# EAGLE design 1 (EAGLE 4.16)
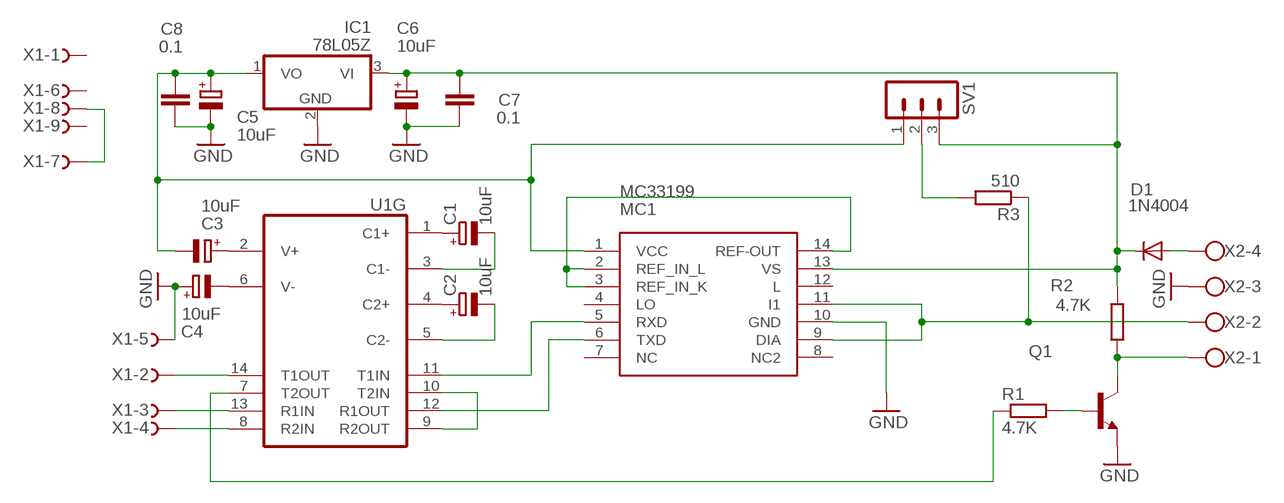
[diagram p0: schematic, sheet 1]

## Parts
C1  10uF  CPOL-EUE2-4  [E2-4]
C2  10uF  CPOL-EUE2-4  [E2-4]
C3  10uF  CPOL-EUE2-4  [E2-4]
C4  10uF  CPOL-EUE2-4  [E2-4]
C5  10uF  CPOL-EUE2-4  [E2-4]
C6  10uF  CPOL-EUE2-4  [E2-4]
C7  0.1  C-EU050-024X044  [C050-024X044]
C8  0.1  C-EU050-024X044  [C050-024X044]
D1  1N4004  [DO41-10]
IC1  78L05Z  [TO92]
MC1  MC33199  [SO14]
Q1  BF459  [TO126]
R1  4.7K  R-EU_0207/10  [0207/10]
R2  4.7K  R-EU_0207/10  [0207/10]
R3  510  R-EU_0207/10  [0207/10]
SV1  MA03-1  [MA03-1]
U1  MAX3232S  [SO16]
X1  F09HPS  [F09HP]
X2  W237-4  [W237-4]

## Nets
12V: C6.+ C7.2 D1.C IC1.3(VI) MC1.13(VS) R2.2 SV1.3
16: R1.1 U1.7(G:T2OUT)
18: MC1.5(RXD) U1.11(G:T1IN)
19: MC1.6(TXD) U1.12(G:R1OUT)
GND: C4.+ C5.- C6.- C7.1 C8.1 IC1.2(GND) MC1.10(GND) Q1.1(E) X1.5 X2.3
N$1: C1.+ U1.1(G:C1+)
N$2: C1.- U1.3(G:C1-)
N$3: C2.+ U1.4(G:C2+)
N$4: C2.- U1.5(G:C2-)
N$5: C3.+ U1.2(G:V+)
N$6: C4.- U1.6(G:V-)
N$7: U1.14(G:T1OUT) X1.2
N$8: R3.2 SV1.2
N$9: U1.13(G:R1IN) X1.3
N$10: U1.8(G:R2IN) X1.4
N$11: U1.9(G:R2OUT) U1.10(G:T2IN)
N$12: D1.A X2.4
N$13: MC1.2(REF_IN_L) MC1.3(REF_IN_K) MC1.14(REF-OUT)
N$14: Q1.3(B) R1.2
N$15: Q1.2(C) R2.1 X2.1
N$16: X1.7 X1.8
N$20: MC1.9(DIA) MC1.11(I1) R3.1 X2.2
VCC: C3.- C5.+ C8.2 IC1.1(VO) MC1.1(VCC) SV1.1
Unconnected: MC1.4(LO) MC1.7(NC) MC1.8(NC2) MC1.12(L) X1.1 X1.6 X1.9

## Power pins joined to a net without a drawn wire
GND: U1.15(P:GND)
VCC: U1.16(P:VCC)

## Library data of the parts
C1-C6 = rcl:CPOL-EU: POLARIZED CAPACITOR, European symbol
C7 C8 = rcl:C-EU: CAPACITOR, European symbol
D1 = diode:1N4004: DIODE
IC1 = linear:78*: Positive VOLTAGE REGULATOR Source: http://cache.national.com/ds/LM/LM78L05.pdf http://www.fairchildsemi.com/ds/LM/LM7805.pdf
MC1 = LevoROMS:MC33199
Q1 = transistor-npn:BF459*: NPN Transistor
R1-R3 = rcl:R-EU_: RESISTOR, European symbol
SV1 = con-lstb:MA03-1: PIN HEADER
U1 = m-pad-2.1:MAX3232: max3232CD or max3232ID digikey parts: 296-13094-1-ND and 296-13098-1-ND respectively ~$2.60 (both 16pin soic narrow, but with different temperature grades) Texas Instruments 3V to 5.5V 250kbit multichannel RS-232 line driver/receiver with +-15kV ESD protection available as TI samples and digikey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
X1 = con-subd:F09?S: SUB-D
X2 = con-wago-500:W237-4: WAGO SCREW CLAMP

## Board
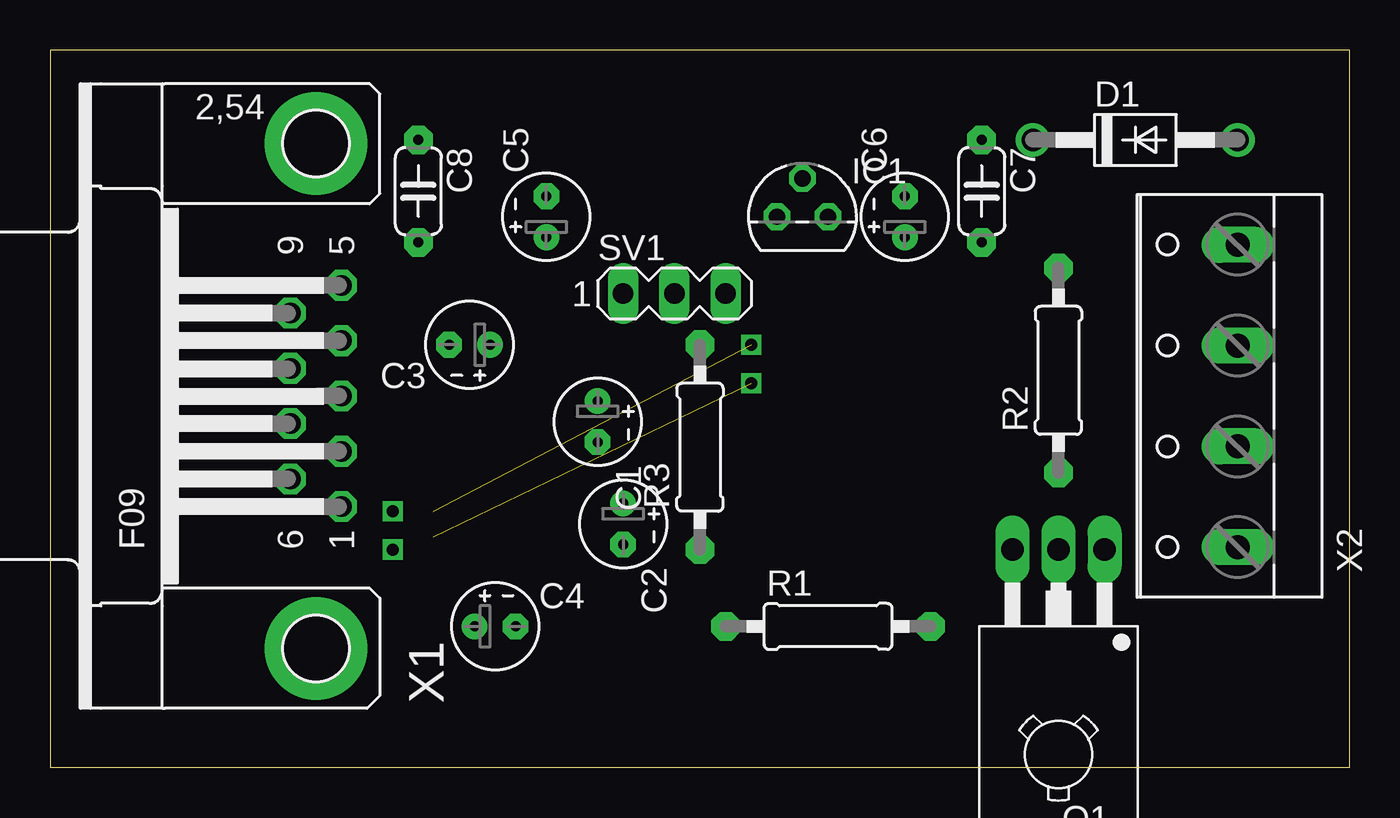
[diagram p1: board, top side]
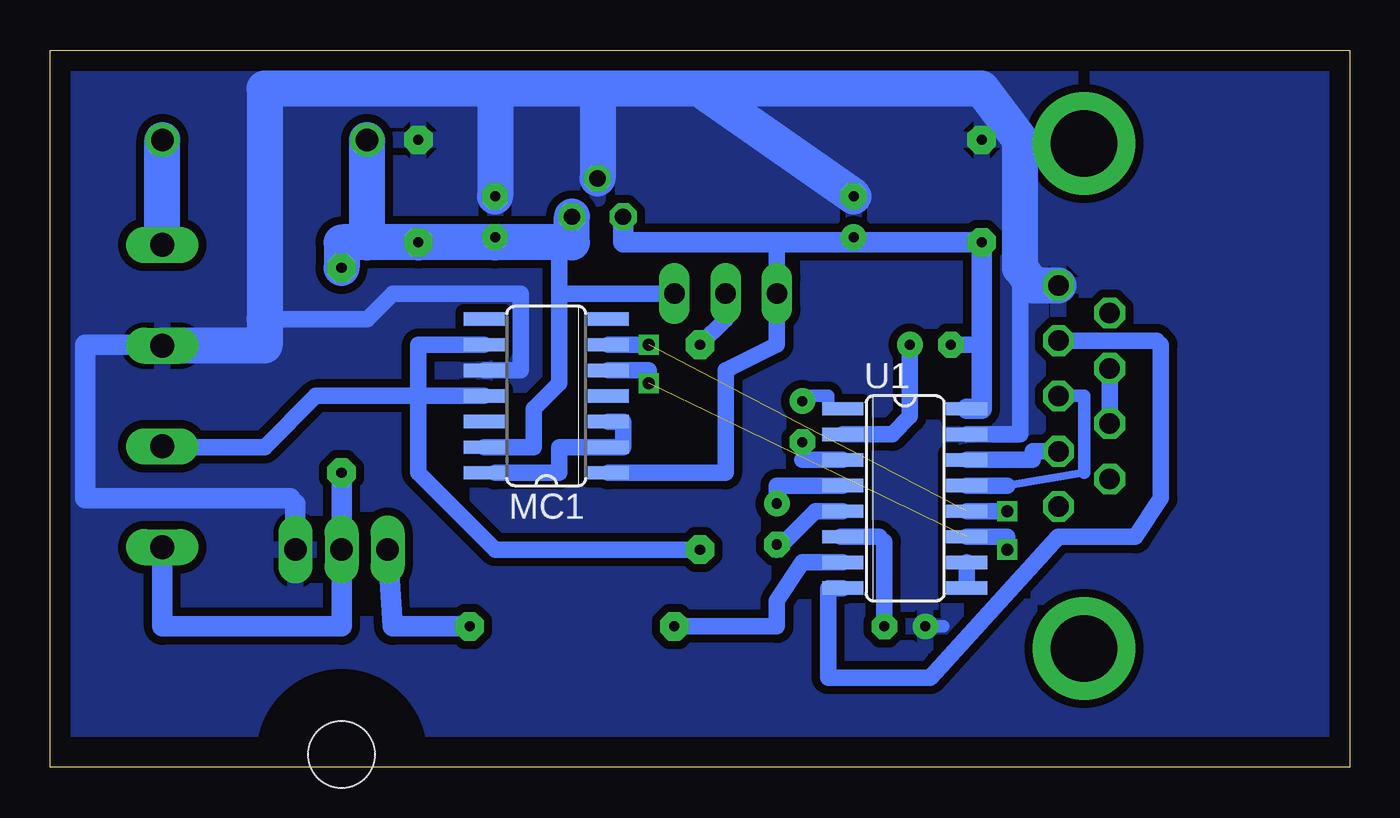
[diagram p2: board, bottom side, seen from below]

Size 64.44 x 35.55 mm. Coordinates in mm from the lower left corner, seen from the top.
Outline: 0,0 64.44,0 64.44,35.55 0,35.55 0,0
Copper layers (1*16): Top 0.035mm / dielectric 1.5mm / Bottom 0.035mm
Design rules "default": minimum track width 10mil, minimum drill 24mil, track to track 8mil, track to pad 8mil, pad to pad 8mil, via to via 8mil, smd to smd 8mil, copper to edge 40mil, drill to drill 8mil, minimum pad ring 10mil, minimum via ring 8mil, stop-mask expansion 4mil, vias tented up to drill 0mil, thermal gap 10mil

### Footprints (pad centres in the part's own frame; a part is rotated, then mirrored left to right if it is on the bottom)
E2-4 = drill 0.5 pad 1.27 round: + -1.016,0 | drill 0.5 pad 1.27 octagon: - 1.016,0
C050-024X044 = drill 0.5 pad 1.422 octagon: 1 -2.54,0; 2 2.54,0
DO41-10 = drill 1.118 round: A 5.08,0; C -5.08,0
TO92 = drill 0.813 octagon: 1 -1.27,0; 2 0,1.905; 3 1.27,0
SO14 = smd 0.66 x 2.032: 1 -3.81,-3.073; 2 -2.54,-3.073; 3 -1.27,-3.073; 4 0,-3.073; 5 1.27,-3.073; 6 2.54,-3.073; 7 3.81,-3.073; 8 3.81,3.073; 9 2.54,3.073; 10 1.27,3.073; 11 0,3.073; 12 -1.27,3.073; 13 -2.54,3.073; 14 -3.81,3.073
TO126 = drill 1.118 long: 1 -2.286,-5.08; 2 0,-5.08; 3 2.286,-5.08 | hole 3.302: 0,5.08
0207/10 = drill 0.5 pad 1.422 octagon: 1 -5.08,0; 2 5.08,0
MA03-1 = drill 1.016 long: 1 -2.54,0; 2 0,0; 3 2.54,0
SO16 = smd 0.66 x 2.032: 1 -4.445,-3.073; 2 -3.175,-3.073; 3 -1.905,-3.073; 4 -0.635,-3.073; 5 0.635,-3.073; 6 1.905,-3.073; 7 3.175,-3.073; 8 4.445,-3.073; 9 4.445,3.073; 10 3.175,3.073; 11 1.905,3.073; 12 0.635,3.073; 13 -0.635,3.073; 14 -1.905,3.073; 15 -3.175,3.073; 16 -4.445,3.073
F09HP = drill 1.016 octagon: 1 -5.486,-1.27; 2 -2.743,-1.27; 3 0,-1.27; 4 2.743,-1.27; 5 5.486,-1.27; 6 -4.115,1.27; 7 -1.372,1.27; 8 1.372,1.27; 9 4.115,1.27 | drill 3.302 pad 5.08 round: G1 -12.522,0; G2 12.522,0
W237-4 = drill 1.194 long: 1 -7.5,-1.27; 2 -2.5,-1.27; 3 2.5,-1.27; 4 7.5,-1.27

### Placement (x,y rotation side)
C1  27.14,17.14 270 top
C2  28.41,12.06 270 top
C3  20.79,20.95 180 top
C4  22.06,6.98 0 top
C5  24.6,27.3 90 top
C6  42.38,27.3 90 top
C7  46.19,28.57 270 top
C8  18.25,28.57 270 top
D1  53.81,31.11 0 top
IC1  37.3,27.3 0 top
MC1  39.84,18.41 90 bottom
Q1  50,5.71 180 top
R1  38.57,6.98 0 top
R2  50,19.68 90 top
R3  32.22,15.87 90 top
SV1  30.95,23.49 0 top
U1  22.06,13.33 270 bottom
X1  13.17,18.41 90 top
X2  57.62,18.41 90 top

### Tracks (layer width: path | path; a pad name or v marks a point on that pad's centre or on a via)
12V
  Bottom 0.406: 42.38,26.03 C6.+
  Bottom 0.813: MC1.13 40.47,15.87 40.47,17.77 39.2,19.05 39.2,23.49 | 39.2,23.49 39.2,26.03 | 39.2,23.49 SV1.3
  Bottom 1.016: 39.2,26.03 38.57,26.03
  Bottom 1.778: 38.57,26.03 IC1.3 | 39.2,26.03 42.38,26.03 C7.2 48.73,26.03 | 48.73,26.03 50,26.03 R2.2 | 48.73,26.03 D1.C
16
  Bottom 0.813: U1.7 27.14,10.16 28.41,8.25 28.41,6.98 R1.1
18  (via drill 0.6)  (1 unrouted)
  Bottom 0.813: U1.11 16.98,11.43 v16.98,10.79 | MC1.5 34.76,19.68 v34.76,19.05
19  (via drill 0.6)  (1 unrouted)
  Bottom 0.813: v16.98,12.7 U1.12 | v34.76,20.95 MC1.6
GND
  Bottom 0.406: 52.54,13.33 52.29,13.08 | X2.3 58.89,20.95
  Bottom 0.61: 20.15,6.98 C4.+
  Bottom 0.813: U1.15 16.34,16.51 16.34,24.76 | MC1.10 41.11,19.68 41.11,23.49 47.46,23.49 48.73,22.22 53.81,22.22
  Bottom 1.016: 52.29,13.08 Q1.1 | 52.54,13.33 62.7,13.33 62.7,20.95 58.89,20.95
  Bottom 1.778: X1.5 15.71,23.9 16.34,24.76 16.34,31.11 18.25,33.65 32.22,33.65 | X2.3 53.81,20.91 53.81,22.22 53.81,33.65 42.38,33.65 | 42.38,33.65 C6.- | 32.22,33.65 37.3,33.65 | 37.3,33.65 42.38,33.65 | 32.22,33.65 C5.- | 37.3,33.65 IC1.2
  pour Bottom (isolate 0.406): 0.47,34.92 0.47,1.9 63.97,1.9 63.97,34.92
N$1
  Bottom 0.406: U1.1 25.87,17.77 | 27.14,18.41 C1.+
  Bottom 0.61: 25.87,17.77 25.87,18.41 27.14,18.41
N$2
  Bottom 0.61: 27.14,15.23 C1.-
  Bottom 0.813: U1.3 27.14,15.23
N$3
  Bottom 0.813: U1.4 28.41,13.96 C2.+
N$4
  Bottom 0.813: U1.5 26.5,12.7 28.41,10.79 C2.-
N$5
  Bottom 0.813: U1.2 22.69,16.51 21.81,17.39 C3.+
N$6
  Bottom 0.61: 23.08,11.17 23.33,11.43
  Bottom 0.813: C4.- 23.08,11.17 | 25.24,11.43 U1.6 23.33,11.43
N$7
  Bottom 0.813: U1.14 15.71,15.23 15.71,15.67 X1.2
N$8
  Bottom 0.813: R3.2 30.95,22.22 SV1.2
N$9
  Bottom 0.406: 13.17,14.6 16.98,13.96
  Bottom 0.61: 13.17,14.6 13.17,18.41 X1.3
  Bottom 0.813: 16.98,13.96 U1.13
N$10
  Bottom 0.813: X1.4 9.56,21.15 9.36,20.95 9.36,13.33 10.63,11.43 14.44,11.43 20.79,4.44 25.87,4.44 25.87,8.88 U1.8
N$11
  Bottom 0.406: U1.9 18.88,8.88 18.99,8.99
  Bottom 0.813: U1.10 18.99,8.99
N$12
  Bottom 1.778: X2.4 D1.A
N$13
  Bottom 0.406: MC1.14 43.02,14.6
  Bottom 0.61: 42.38,14.6 MC1.14
  Bottom 0.813: MC1.3 36.03,17.14 36.03,15.87 MC1.2 39.2,15.87 39.2,14.6 42.38,14.6
N$14
  Bottom 1.016: Q1.3 47.46,6.98 R1.2
N$15
  Bottom 1.016: R2.1 Q1.2 50,6.98 58.89,6.98 X2.1
N$16
  Bottom 0.813: X1.7 X1.8
N$20
  Bottom 0.406: 58.89,15.87 X2.2 | MC1.11 42.38,18.41
  Bottom 0.813: 58.89,15.87 53.81,15.87 51.27,18.41 46.19,18.41 | 46.19,18.41 MC1.11 | MC1.9 46.19,20.95 46.19,18.41 | R3.1 42.38,10.79 46.19,14.6 46.19,18.41
VCC
  Bottom 0.406: 32.22,26.03 C5.+
  Bottom 0.813: 28.41,26.03 SV1.1 28.41,20.95 30.95,19.68 30.95,14.6 MC1.1 | 18.25,20.95 C3.-
  Bottom 1.016: U1.16 18.25,17.77 18.25,20.95 C8.2 28.41,26.03 32.22,26.03 36.03,26.03 IC1.1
